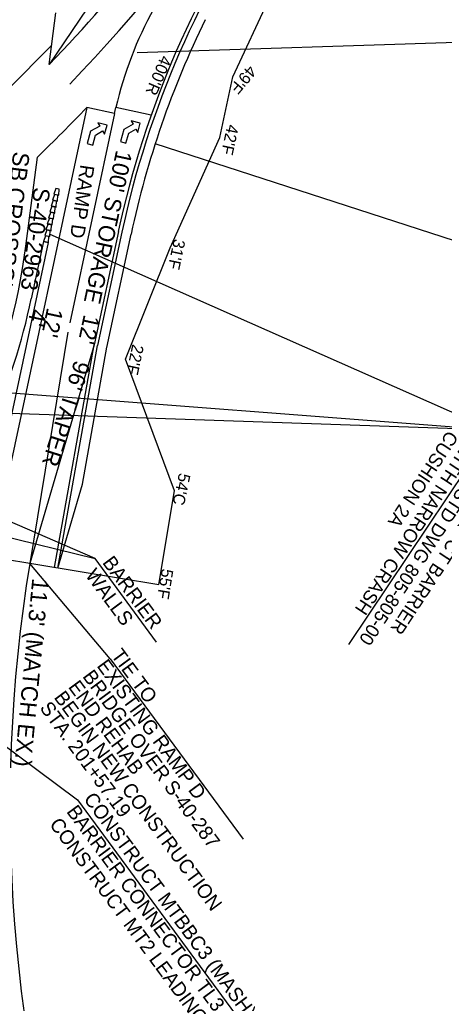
# Model space of a CAD drawing. Extents: x 1966090 to 1975830, y 788086 to 801233.
# Drawn here: x 1971594 to 1971773.6, y 795877.6 to 796293.3 of the extents above; entities that cross this region are included whole.
import ezdxf

# ---------------------------------------------------------------- set-up
doc = ezdxf.new("R2010")
doc.units = 0
for name, color, linetype in [('BR_PRESTRESSED BEAM', 7, 'Continuous'), ('BR_PROPOSED_DRAINAGE', 7, 'Continuous'), ('BR_REBAR', 7, 'Continuous'), ('RD_EX_Driveway_txCode', 7, 'Continuous'), ('RD_EX_RW_TX', 7, 'Continuous'), ('RD_EX_SU_Gas', 7, 'Continuous'), ('RD_EX_TX_BldgApp_ELEV', 7, 'Continuous'), ('RD_PD_PaveShd', 7, 'Continuous'), ('RD_PD_RW_TX', 7, 'Continuous'), ('RD_Sketch6', 7, 'Continuous'), ('RD_Sketch8', 7, 'Continuous')]:
    doc.layers.add(name, color=color, linetype=linetype)

msp = doc.modelspace()

# ---------------------------------------------------------------- linework, layer by layer
at = {"layer": 'BR_PRESTRESSED BEAM'}
for p, q in [((1971630.85, 796154.74), (1971641.1, 796202.62)), ((1971620.55, 796096.99), (1971630.87, 796154.88)), ((1971610.16, 796061.48), (1971620.53, 796096.99))]:
    msp.add_line(p, q, dxfattribs=at)
msp.add_arc((1972026.85, 796120.01), 394.5, 153.9429, 167.9132, dxfattribs=at)
at = {"layer": 'BR_PROPOSED_DRAINAGE'}
for p, q in [((1971684.14, 796269.17), (1971707.03, 796318.32)), ((1971678.64, 796243.52), (1971684.14, 796269.17)), ((1971657.65, 796196.88), (1971678.64, 796243.52)), ((1971638.8, 796149.78), (1971657.65, 796196.88)), ((1971659.45, 796094.22), (1971638.8, 796149.78)), ((1971652.78, 796054.64), (1971659.45, 796094.22)), ((1971576.55, 796067.27), (1971652.78, 796054.62))]:
    msp.add_line(p, q, dxfattribs=at)
at = {"layer": 'BR_REBAR'}
for p, q in [((1971606.09, 796199.13), (1971584.48, 796098.2)), ((1971604.05, 796199.57), (1971598.92, 796175.33)), ((1971606.09, 796199.13), (1971604.05, 796199.57))]:
    msp.add_line(p, q, dxfattribs=at)
msp.add_arc((1971332.81, 796231.61), 272, 336.2104, 348.0583, dxfattribs=at)
at = {"layer": 'RD_EX_Driveway_txCode'}
for p, q in [((1971627.89, 796248.36), (1971624, 796246.13)), ((1971630.94, 796248.73), (1971627.08, 796249.77)), ((1971627.08, 796249.77), (1971627.89, 796248.36)), ((1971629.89, 796244.87), (1971630.94, 796248.73)), ((1971641.94, 796249.18), (1971638.05, 796246.95)), ((1971644.99, 796249.54), (1971641.13, 796250.59)), ((1971641.13, 796250.59), (1971641.94, 796249.18)), ((1971643.94, 796245.68), (1971644.99, 796249.54)), ((1971624, 796246.13), (1971622.6, 796240.97)), ((1971624.91, 796240.34), (1971626.06, 796244.56)), ((1971626.06, 796244.56), (1971629.08, 796246.28)), ((1971629.08, 796246.28), (1971629.89, 796244.87)), ((1971638.05, 796246.95), (1971636.65, 796241.79)), ((1971638.96, 796241.16), (1971640.11, 796245.38)), ((1971640.11, 796245.38), (1971643.13, 796247.09)), ((1971643.13, 796247.09), (1971643.94, 796245.68)), ((1971622.6, 796240.97), (1971624.91, 796240.34)), ((1971636.65, 796241.79), (1971638.96, 796241.16))]:
    msp.add_line(p, q, dxfattribs=at)
at = {"layer": 'RD_EX_SU_Gas'}
for p, q in [((1971607.58, 796282.5), (1971589.03, 796263.74)), ((1971634.14, 796253.69), (1971615.18, 796165.16)), ((1971634.14, 796253.69), (1971622.4, 796256.2)), ((1971634.14, 796253.69), (1971634.67, 796256.19)), ((1971649.6, 796252.99), (1971634.67, 796256.19)), ((1971614.35, 796161.27), (1971598.28, 796063.55))]:
    msp.add_line(p, q, dxfattribs=at)
for centre, radius, start, end in [((1971051.22, 796804.85), 780, 316.30752, 334.3781), ((1971051.22, 796804.85), 768, 316.30752, 326.01649), ((1971790.59, 796220.19), 160, 150.9704, 166.9987), ((1974296, 798203.94), 3784.72, 216.39766, 226.1479), ((1974296, 798203.94), 3784.72, 216.39766, 236.97136), ((1974296, 798203.94), 3796.72, 216.39766, 236.97136), ((1974296, 798203.94), 3842.72, 216.39766, 244.09898), ((1974296, 798203.94), 3854.72, 216.39766, 243.9112)]:
    msp.add_arc(centre, radius, start, end, dxfattribs=at)
at = {"layer": 'RD_EX_TX_BldgApp_ELEV'}
for p, q in [((1971608.73, 796219.48), (1971607.84, 796217.06)), ((1971609.27, 796221.97), (1971608.38, 796219.55)), ((1971608.38, 796219.55), (1971610.52, 796219.09)), ((1971610.16, 796219.17), (1971608.73, 796219.48)), ((1971610.7, 796221.67), (1971609.27, 796221.97)), ((1971609.98, 796216.59), (1971610.16, 796219.17)), ((1971610.52, 796219.09), (1971610.7, 796221.67)), ((1971608.19, 796216.98), (1971607.3, 796214.56)), ((1971607.84, 796217.06), (1971609.98, 796216.59)), ((1971609.62, 796216.67), (1971608.19, 796216.98)), ((1971609.44, 796214.1), (1971609.62, 796216.67)), ((1971607.11, 796211.98), (1971606.21, 796209.56)), ((1971607.65, 796214.48), (1971606.75, 796212.06)), ((1971606.75, 796212.06), (1971608.9, 796211.6)), ((1971608.54, 796211.67), (1971607.11, 796211.98)), ((1971607.3, 796214.56), (1971609.44, 796214.1)), ((1971609.08, 796214.17), (1971607.65, 796214.48)), ((1971608.35, 796209.1), (1971608.54, 796211.67)), ((1971608.9, 796211.6), (1971609.08, 796214.17)), ((1971606.03, 796206.99), (1971605.13, 796204.57)), ((1971606.57, 796209.49), (1971605.67, 796207.07)), ((1971605.67, 796207.07), (1971607.81, 796206.6)), ((1971607.46, 796206.68), (1971606.03, 796206.99)), ((1971606.21, 796209.56), (1971608.35, 796209.1)), ((1971608, 796209.18), (1971606.57, 796209.49)), ((1971607.27, 796204.1), (1971607.46, 796206.68)), ((1971607.28, 796209.33), (1971607.28, 796209.33)), ((1971607.81, 796206.6), (1971608, 796209.18)), ((1971605.49, 796204.49), (1971604.59, 796202.07)), ((1971605.13, 796204.57), (1971607.27, 796204.1)), ((1971606.92, 796204.18), (1971605.49, 796204.49)), ((1971606.73, 796201.61), (1971606.92, 796204.18)), ((1971604.95, 796201.99), (1971604.05, 796199.57)), ((1971604.05, 796199.57), (1971606.19, 796199.11)), ((1971604.59, 796202.07), (1971606.73, 796201.61)), ((1971606.38, 796201.68), (1971604.95, 796201.99)), ((1971606.19, 796199.11), (1971606.38, 796201.68))]:
    msp.add_line(p, q, dxfattribs=at)
at = {"layer": 'RD_PD_PaveShd'}
msp.add_line((1971608.68, 796061.77), (1971625.46, 796155.84), dxfattribs=at)
at = {"layer": 'RD_PD_RW_TX'}
for p in [(1971637.19, 796203.46), (1971610.16, 796061.51)]:
    msp.add_line(p, (1971626.93, 796155.58), dxfattribs=at)
msp.add_arc((1972026.85, 796120.01), 398.5, 144.9337, 167.9132, dxfattribs=at)
at = {"layer": 'RD_Sketch6'}
for p, q in [((1971932.18, 796288.53), (1971643.71, 796279.28)), ((1971891.84, 796162.89), (1971651.31, 796240.83)), ((1971793.86, 796119.85), (1971606.84, 796202.55)), ((1971793.86, 796119.85), (1971588.72, 796135.58)), ((1971793.86, 796119.85), (1971590.01, 796126.9)), ((1971733.2, 796029.28), (1971793.86, 796119.85)), ((1971625.88, 796065.55), (1971579.8, 796085.49)), ((1971565.95, 796080.29), (1971625.88, 796065.55)), ((1971651.89, 796030.27), (1971625.88, 796065.55)), ((1971632.29, 796023.21), (1971598.32, 796063.54)), ((1971632.29, 796023.21), (1971688.48, 795946.99)), ((1971546.41, 796017.16), (1971618.5, 795963.59)), ((1971618.5, 795963.59), (1971716.63, 795830.48))]:
    msp.add_line(p, q, dxfattribs=at)
at = {"layer": 'RD_Sketch8'}
for p, q in [((1971678.92, 796381.72), (1971606.52, 796274.32)), ((1971606.52, 796274.32), (1971609.35, 796296.26)), ((1971622.4, 796256.2), (1971588.39, 796097.36)), ((1971596.62, 796197.58), (1971601.48, 796235.22)), ((1971635.72, 796203.77), (1971625.47, 796155.89)), ((1971625.47, 796155.89), (1971598.28, 796063.55))]:
    msp.add_line(p, q, dxfattribs=at)
for centre, radius, start, end in [((1972026.85, 796120.01), 400, 144.9337, 167.9132), ((1971051.22, 796804.85), 792, 314.00956, 316.15347), ((1971332.81, 796231.61), 266, 336.2104, 352.6496), ((1972226.58, 795960.7), 652.66, 167.91315, 225.41147), ((1972226.58, 795960.7), 636.66, 170.70317, 225.41147), ((1974296, 798203.94), 3808.72, 216.39766, 236.97136), ((1974296, 798203.94), 3830.72, 216.39766, 243.9112), ((1972046.23, 795651.96), 636.62, 156.21044, 245.71509), ((1974296, 798203.94), 3878.72, 216.39766, 241.30888), ((1972046.23, 795651.96), 620.62, 156.21044, 245.71509)]:
    msp.add_arc(centre, radius, start, end, dxfattribs=at)

# ---------------------------------------------------------------- texts
at = {"layer": 'RD_EX_Driveway_txCode'}
for s, height, rotation, p in [('SB CROSSOVER', 7, 262.651, (1971591.36, 796237.79)), ("100' STORAGE", 7, 257.9132, (1971634.85, 796238.45)), ('RAMP D', 6, 261.821, (1971619.71, 796232.27)), ('S-40-2963', 7, 262.651, (1971600.01, 796222.74)), ("4'", 7, 257.9132, (1971598.73, 796171.37)), ("12'", 7, 257.9132, (1971605.66, 796171.89)), ("12'", 7, 257.9132, (1971621.18, 796168.95)), ("96' TAPER", 7, 252.3897, (1971617.26, 796149.71)), ("11.3' (MATCH EX.)", 7, 264.5357, (1971599.36, 796057.41)), ('S-40-287 (ARROWWOOD ROAD)', 5.9996, 222.6982, (1971820.63, 795905.2))]:
    msp.add_text(s, height=height, rotation=rotation, dxfattribs=at).set_placement(p)
at = {"layer": 'RD_EX_RW_TX'}
for s, rotation, p in [("49'F", 229.757, (1971690.81, 796274.45)), ("42'F", 257.9132, (1971681.8, 796249.28)), ("31'F", 257.9132, (1971659.24, 796200.87)), ("22'F", 257.9132, (1971641.69, 796156.38)), ("54'C", 257.9132, (1971661.4, 796101.97)), ("55'F", 260.7024, (1971654.11, 796061.53))]:
    msp.add_text(s, height=5, rotation=rotation, dxfattribs=at).set_placement(p)
at = {"layer": 'RD_Sketch6'}
for s, height, rotation, p in [("400'R", 5, 246.9232, (1971653.83, 796278.58)), ('CUSHION 2A', 5.7, 236.7151, (1971775.02, 796120.07)), ('WITH NARROW CRASH', 5.6996, 236.7151, (1971782.16, 796115.38)), ('PER STD DWG 805-805-00', 5.6996, 236.7151, (1971789.31, 796110.68)), ('CONSTRUCT BARRIER ', 5.6996, 236.7151, (1971796.46, 796105.99)), ('BARRIER', 6, 306.4243, (1971628.73, 796063.85)), ('WALLS', 6, 306.4243, (1971621.49, 796058.5)), ('TIE TO ', 6, 306.3977, (1971632.41, 796024.66)), ('EXISTING RAMP D', 6, 306.3977, (1971626.37, 796020.21)), ('BRIDGE OVER S-40-287', 6, 306.3977, (1971620.33, 796015.76)), ('END REHAB', 6, 306.3977, (1971614.3, 796011.31)), ('BEGIN NEW CONSTRUCTION', 6, 306.3977, (1971608.26, 796006.86)), ('STA. 201+57.19', 6, 306.3977, (1971602.22, 796002.41)), ('CONSTRUCT MTBBC3 (MASH) THRIE-BEAM', 5.9996, 306.4243, (1971620.8, 795963.95)), ('BARRIER CONNECTOR TL3', 5.9996, 306.4243, (1971613.56, 795958.61)), ('CONSTRUCT MT2 LEADING END TREATMENT', 5.9996, 306.4243, (1971606.32, 795953.26))]:
    msp.add_text(s, height=height, rotation=rotation, dxfattribs=at).set_placement(p)

doc.saveas('drawing.dxf')
